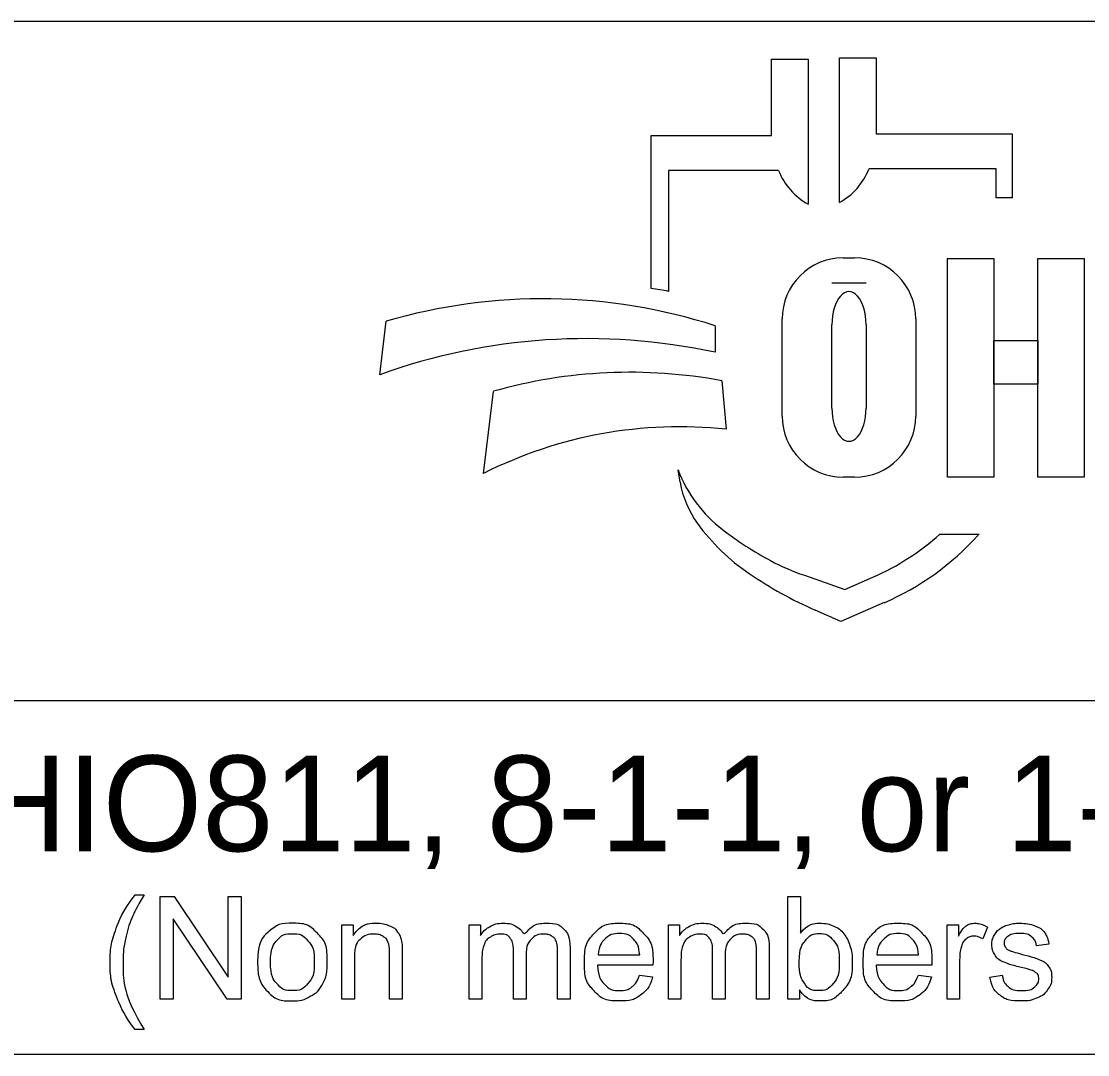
# Model space of a CAD drawing. Extents: x -107 to 120, y -81 to 213.
# Drawn here: x 6.525 to 8.085, y 3.711 to 5.224 of the extents above; entities that cross this region are included whole.
import ezdxf

# ---------------------------------------------------------------- set-up
doc = ezdxf.new("R2010")
doc.units = 0
doc.layers.add('SH_Data', color=7, linetype='Continuous')
doc.layers.add('SH_Text', color=7, linetype='Continuous')

msp = doc.modelspace()

# ---------------------------------------------------------------- linework, layer by layer
at = {"layer": 'SH_Data'}
for p, q in [((6.2665, 5.2235), (10.5165, 5.2235)), ((10.5165, 4.2288), (6.2665, 4.2288)), ((10.5165, 3.711), (6.2665, 3.711))]:
    msp.add_line(p, q, dxfattribs=at)
at = {"layer": 'SH_Text'}
for p, q in [((7.6225, 5.0565), (7.6225, 5.168)), ((7.6225, 5.168), (7.6762, 5.168)), ((7.6762, 5.168), (7.6762, 4.9559)), ((7.7218, 4.9582), (7.7218, 5.1703)), ((7.7218, 5.1703), (7.7755, 5.1703)), ((7.7755, 5.1703), (7.7755, 5.0588)), ((7.4466, 4.8326), (7.4466, 5.0565)), ((7.4466, 5.0565), (7.6225, 5.0565)), ((7.7755, 5.0588), (7.9747, 5.0588)), ((7.9747, 5.0588), (7.9747, 4.965)), ((7.4718, 5.005), (7.4718, 4.8282)), ((7.6329, 5.005), (7.4718, 5.005)), ((7.9514, 5.0074), (7.7651, 5.0074)), ((7.9514, 4.965), (7.9514, 5.0074)), ((7.9747, 4.965), (7.9514, 4.965)), ((7.7275, 4.8773), (7.7441, 4.8773)), ((7.7608, 4.8403), (7.711, 4.8403)), ((7.0492, 4.7063), (7.0586, 4.7844)), ((7.5399, 4.7779), (7.5399, 4.7391)), ((7.6381, 4.6458), (7.6381, 4.7878)), ((7.711, 4.6572), (7.711, 4.7795)), ((7.7608, 4.7795), (7.7608, 4.6572)), ((7.8335, 4.7878), (7.8335, 4.6458)), ((7.5498, 4.6973), (7.5561, 4.6264)), ((7.201, 4.5618), (7.2157, 4.6819)), ((7.4887, 4.5489), (7.4857, 4.5668)), ((7.7441, 4.5563), (7.7275, 4.5563)), ((7.869, 4.473), (7.9264, 4.473)), ((7.6706, 4.4126), (7.73, 4.3921)), ((7.73, 4.3921), (7.771, 4.4099)), ((7.7873, 4.3726), (7.724, 4.3451)), ((7.724, 4.3451), (7.6866, 4.3615))]:
    msp.add_line(p, q, dxfattribs=at)
for points in [[(7.88, 4.8763), (7.9479, 4.8763), (7.9479, 4.5563), (7.88, 4.5563)], [(8.0121, 4.8763), (8.0801, 4.8763), (8.0801, 4.5563), (8.0121, 4.5563)], [(7.9479, 4.7564), (8.0121, 4.7564), (8.0121, 4.6924), (7.9479, 4.6924)]]:
    msp.add_lwpolyline(points, close=True, dxfattribs=at)
for points in [[(6.6911, 3.9448), (6.7043, 3.9448)], [(6.7279, 3.7921), (6.7279, 3.9423), (6.7482, 3.9423), (6.8272, 3.8243), (6.8272, 3.9423), (6.8462, 3.9423), (6.8462, 3.7921), (6.8259, 3.7921), (6.7469, 3.91), (6.7469, 3.7921), (6.7279, 3.7921)], [(7.6633, 3.7921), (7.6463, 3.7921), (7.6463, 3.9423), (7.6647, 3.9423), (7.6647, 3.8887)], [(6.9938, 3.7921), (6.9938, 3.9009), (7.0104, 3.9009), (7.0104, 3.8855)], [(7.1802, 3.7921), (7.1802, 3.9009), (7.1967, 3.9009), (7.1967, 3.8856)], [(7.4716, 3.7921), (7.4716, 3.9009), (7.4881, 3.9009), (7.4881, 3.8856)], [(7.8794, 3.7921), (7.8794, 3.9009), (7.896, 3.9009), (7.896, 3.8845)], [(7.9384, 3.8975), (7.932, 3.8804)], [(8.0284, 3.8728), (8.0103, 3.8704)], [(7.0822, 3.859), (7.0822, 3.7921), (7.0637, 3.7921), (7.0637, 3.8582)], [(7.2633, 3.8553), (7.2633, 3.7921), (7.2449, 3.7921), (7.2449, 3.8628)], [(7.3277, 3.8668), (7.3277, 3.7921), (7.3093, 3.7921), (7.3093, 3.8606)], [(7.3689, 3.8569), (7.4296, 3.8569)], [(7.5547, 3.8553), (7.5547, 3.7921), (7.5363, 3.7921), (7.5363, 3.8628)], [(7.6191, 3.8668), (7.6191, 3.7921), (7.6007, 3.7921), (7.6007, 3.8606)], [(7.7768, 3.8569), (7.8376, 3.8569)], [(7.0122, 3.8515), (7.0122, 3.7921), (6.9938, 3.7921)], [(7.1987, 3.8485), (7.1987, 3.7921), (7.1802, 3.7921)], [(7.449, 3.8418), (7.3678, 3.8418)], [(7.49, 3.8485), (7.49, 3.7921), (7.4716, 3.7921)], [(7.857, 3.8418), (7.7758, 3.8418)], [(7.8978, 3.8491), (7.8978, 3.7921), (7.8794, 3.7921)], [(7.4294, 3.8272), (7.4485, 3.8248)], [(7.8374, 3.8272), (7.8565, 3.8248)], [(7.942, 3.8246), (7.9602, 3.8275)], [(7.6633, 3.8057), (7.6633, 3.7921)], [(6.7043, 3.7479), (6.6911, 3.7479)]]:
    msp.add_lwpolyline(points, dxfattribs=at)
for centre, radius, start, end in [((7.7243, 5.0418), 0.0985, 201.9296, 240.7469), ((7.6737, 5.0441), 0.0985, 299.2531, 338.0704), ((7.7275, 4.7878), 0.0895, 90, 180), ((7.7441, 4.7878), 0.0895, 0, 90), ((7.3184, 4.0236), 0.8191, 79.2074, 81.0007), ((7.2887, 3.9983), 0.8191, 72.1402, 106.3144), ((7.3517, 3.8672), 0.8919, 77.8238, 109.8274), ((7.4156, 3.9776), 0.7322, 79.44, 105.8467), ((7.7275, 4.6458), 0.0895, 180, 270), ((7.7441, 4.6458), 0.0895, 270, 0), ((7.4877, 3.9943), 0.6357, 83.8248, 116.8021), ((7.6731, 4.6389), 0.2008, 201.0457, 232.5314), ((7.63, 4.573), 0.1433, 189.6817, 216.0884), ((7.7637, 4.6704), 0.3088, 216.0884, 235.7167), ((7.8656, 4.8901), 0.5173, 232.5314, 241.794), ((7.6276, 4.7404), 0.3602, 293.4582, 312.0712), ((7.6276, 4.7404), 0.401, 293.4582, 317.8286), ((7.7804, 4.7313), 0.3371, 241.794, 250.9821), ((7.9302, 4.9147), 0.6044, 235.7167, 246.2325)]:
    msp.add_arc(centre, radius, start, end, dxfattribs=at)
for centre, start_param, end_param in [((7.7359, 4.7795), 4.712389, 7.853982), ((7.7359, 4.6572), 1.570796, 4.712389)]:
    msp.add_ellipse(centre, major_axis=(0, 0.0484), ratio=0.514403, start_param=start_param, end_param=end_param, dxfattribs=at)
for points in [[(6.6911, 3.7479), (6.6758, 3.7672), (6.6653, 3.793), (6.6547, 3.8188), (6.6547, 3.8465), (6.6547, 3.8708), (6.6626, 3.8932), (6.6718, 3.9191), (6.6911, 3.9448)], [(6.7043, 3.9448), (6.6919, 3.9235), (6.6879, 3.9144), (6.6817, 3.9002), (6.6781, 3.8849), (6.6737, 3.8657), (6.6737, 3.8464), (6.6737, 3.7971), (6.7043, 3.7479)], [(6.8703, 3.8465), (6.8703, 3.8767), (6.8871, 3.8913), (6.9011, 3.9033), (6.9213, 3.9033), (6.9437, 3.9033), (6.958, 3.8887), (6.9722, 3.874), (6.9722, 3.8481), (6.9722, 3.8271), (6.9659, 3.815), (6.9596, 3.803), (6.9476, 3.7964), (6.9355, 3.7897), (6.9213, 3.7897), (6.8985, 3.7897), (6.8844, 3.8043), (6.8703, 3.819), (6.8703, 3.8465)], [(7.0104, 3.8855), (7.0224, 3.9033), (7.045, 3.9033), (7.0548, 3.9033), (7.0631, 3.8998), (7.0713, 3.8963), (7.0754, 3.8905), (7.0795, 3.8848), (7.0812, 3.8769), (7.0822, 3.8718), (7.0822, 3.859)], [(7.1967, 3.8856), (7.2018, 3.8936), (7.2103, 3.8985), (7.2188, 3.9033), (7.2297, 3.9033), (7.2418, 3.9033), (7.2495, 3.8983), (7.2573, 3.8933), (7.2605, 3.8843), (7.2734, 3.9033), (7.2941, 3.9033), (7.3103, 3.9033), (7.319, 3.8944), (7.3277, 3.8854), (7.3277, 3.8668)], [(7.4485, 3.8248), (7.444, 3.8081), (7.4318, 3.7989), (7.4196, 3.7897), (7.4006, 3.7897), (7.3768, 3.7897), (7.3628, 3.8044), (7.3488, 3.8191), (7.3488, 3.8456), (7.3488, 3.873), (7.363, 3.8882), (7.3771, 3.9033), (7.3996, 3.9033), (7.4214, 3.9033), (7.4353, 3.8885), (7.4491, 3.8736), (7.4491, 3.8467), (7.4491, 3.8451), (7.449, 3.8418)], [(7.4881, 3.8856), (7.4932, 3.8936), (7.5017, 3.8985), (7.5102, 3.9033), (7.5211, 3.9033), (7.5332, 3.9033), (7.5409, 3.8983), (7.5486, 3.8933), (7.5518, 3.8843), (7.5648, 3.9033), (7.5855, 3.9033), (7.6017, 3.9033), (7.6104, 3.8944), (7.6191, 3.8854), (7.6191, 3.8668)], [(7.6647, 3.8887), (7.6764, 3.9033), (7.6945, 3.9033), (7.7045, 3.9033), (7.7135, 3.8993), (7.7224, 3.8953), (7.7282, 3.8879), (7.734, 3.8806), (7.7373, 3.8703), (7.7406, 3.8599), (7.7406, 3.8482), (7.7406, 3.8202), (7.7267, 3.805), (7.7129, 3.7897), (7.6935, 3.7897), (7.6743, 3.7897), (7.6633, 3.8057)], [(7.8565, 3.8248), (7.8519, 3.8081), (7.8398, 3.7989), (7.8276, 3.7897), (7.8086, 3.7897), (7.7848, 3.7897), (7.7708, 3.8044), (7.7568, 3.8191), (7.7568, 3.8456), (7.7568, 3.873), (7.7709, 3.8882), (7.7851, 3.9033), (7.8076, 3.9033), (7.8294, 3.9033), (7.8432, 3.8885), (7.8571, 3.8736), (7.8571, 3.8467), (7.8571, 3.8451), (7.857, 3.8418)], [(7.896, 3.8845), (7.9023, 3.896), (7.9077, 3.8997), (7.9131, 3.9033), (7.9195, 3.9033), (7.9288, 3.9033), (7.9384, 3.8975)], [(7.9602, 3.8275), (7.9617, 3.8165), (7.9688, 3.8107), (7.9758, 3.8048), (7.9884, 3.8048), (8.0012, 3.8048), (8.0073, 3.81), (8.0135, 3.8152), (8.0135, 3.8221), (8.0135, 3.8284), (8.0081, 3.832), (8.0043, 3.8345), (7.9892, 3.8383), (7.9689, 3.8434), (7.961, 3.8471), (7.9532, 3.8508), (7.9491, 3.8574), (7.9451, 3.864), (7.9451, 3.872), (7.9451, 3.8793), (7.9484, 3.8855), (7.9517, 3.8917), (7.9575, 3.8958), (7.9618, 3.8989), (7.9692, 3.9011), (7.9767, 3.9033), (7.9852, 3.9033), (7.998, 3.9033), (8.0077, 3.8997), (8.0174, 3.896), (8.022, 3.8897), (8.0266, 3.8834), (8.0284, 3.8728)], [(6.8893, 3.8465), (6.8893, 3.8256), (6.8984, 3.8152), (6.9075, 3.8048), (6.9213, 3.8048), (6.935, 3.8048), (6.9441, 3.8153), (6.9532, 3.8257), (6.9532, 3.8471), (6.9532, 3.8673), (6.9441, 3.8777), (6.9349, 3.8881), (6.9213, 3.8881), (6.9075, 3.8881), (6.8984, 3.8778), (6.8893, 3.8674), (6.8893, 3.8465)], [(7.0637, 3.8582), (7.0637, 3.8695), (7.0616, 3.8751), (7.0594, 3.8807), (7.054, 3.884), (7.0485, 3.8873), (7.0411, 3.8873), (7.0293, 3.8873), (7.0208, 3.8799), (7.0122, 3.8724), (7.0122, 3.8515)], [(7.2449, 3.8628), (7.2449, 3.875), (7.2404, 3.8812), (7.2359, 3.8873), (7.2256, 3.8873), (7.2178, 3.8873), (7.2112, 3.8832), (7.2046, 3.8791), (7.2016, 3.8713), (7.1987, 3.8634), (7.1987, 3.8485)], [(7.3093, 3.8606), (7.3093, 3.8717), (7.3075, 3.8765), (7.3057, 3.8814), (7.301, 3.8844), (7.2963, 3.8873), (7.29, 3.8873), (7.2785, 3.8873), (7.2709, 3.8797), (7.2633, 3.8721), (7.2633, 3.8553)], [(7.4296, 3.8569), (7.4284, 3.8707), (7.4227, 3.8775), (7.4138, 3.8882), (7.3998, 3.8882), (7.3871, 3.8882), (7.3784, 3.8797), (7.3698, 3.8712), (7.3689, 3.8569)], [(7.5363, 3.8628), (7.5363, 3.875), (7.5318, 3.8812), (7.5272, 3.8873), (7.517, 3.8873), (7.5092, 3.8873), (7.5026, 3.8832), (7.496, 3.8791), (7.493, 3.8713), (7.49, 3.8634), (7.49, 3.8485)], [(7.6007, 3.8606), (7.6007, 3.8717), (7.5989, 3.8765), (7.5971, 3.8814), (7.5924, 3.8844), (7.5877, 3.8873), (7.5813, 3.8873), (7.5699, 3.8873), (7.5623, 3.8797), (7.5547, 3.8721), (7.5547, 3.8553)], [(7.6631, 3.8473), (7.6631, 3.8278), (7.6684, 3.8191), (7.6771, 3.8048), (7.6919, 3.8048), (7.704, 3.8048), (7.7128, 3.8153), (7.7216, 3.8258), (7.7216, 3.8466), (7.7216, 3.8679), (7.7131, 3.8781), (7.7047, 3.8882), (7.6927, 3.8882), (7.6807, 3.8882), (7.6719, 3.8777), (7.6631, 3.8672), (7.6631, 3.8473)], [(7.8376, 3.8569), (7.8364, 3.8707), (7.8306, 3.8775), (7.8218, 3.8882), (7.8078, 3.8882), (7.7951, 3.8882), (7.7864, 3.8797), (7.7778, 3.8712), (7.7768, 3.8569)], [(8.0103, 3.8704), (8.0091, 3.8788), (8.0032, 3.8835), (7.9973, 3.8882), (7.9865, 3.8882), (7.9738, 3.8882), (7.9684, 3.884), (7.9629, 3.8798), (7.9629, 3.8742), (7.9629, 3.8706), (7.9652, 3.8677), (7.9674, 3.8647), (7.9723, 3.8628), (7.975, 3.8618), (7.9886, 3.8581), (8.0082, 3.8529), (8.0159, 3.8495), (8.0237, 3.8462), (8.0281, 3.8399), (8.0325, 3.8335), (8.0325, 3.8241), (8.0325, 3.8149), (8.0271, 3.8067), (8.0217, 3.7986), (8.0116, 3.7942), (8.0014, 3.7897), (7.9886, 3.7897), (7.9673, 3.7897), (7.9562, 3.7985), (7.9451, 3.8073), (7.942, 3.8246)], [(7.932, 3.8804), (7.9253, 3.8843), (7.9185, 3.8843), (7.9125, 3.8843), (7.9077, 3.8807), (7.9029, 3.8771), (7.9009, 3.8706), (7.8978, 3.8608), (7.8978, 3.8491)], [(7.3678, 3.8418), (7.3688, 3.8239), (7.378, 3.8143), (7.3871, 3.8048), (7.4007, 3.8048), (7.4109, 3.8048), (7.418, 3.8102), (7.4252, 3.8155), (7.4294, 3.8272)], [(7.7758, 3.8418), (7.7768, 3.8239), (7.786, 3.8143), (7.7951, 3.8048), (7.8087, 3.8048), (7.8189, 3.8048), (7.826, 3.8102), (7.8332, 3.8155), (7.8374, 3.8272)]]:
    msp.add_open_spline(points, degree=3, dxfattribs=at)

# ---------------------------------------------------------------- texts
msp.add_text('OHIO811, 8-1-1, or 1-800-362-2764', height=0.14, dxfattribs=at).set_placement((6.311, 4.0088))

doc.saveas('drawing.dxf')
